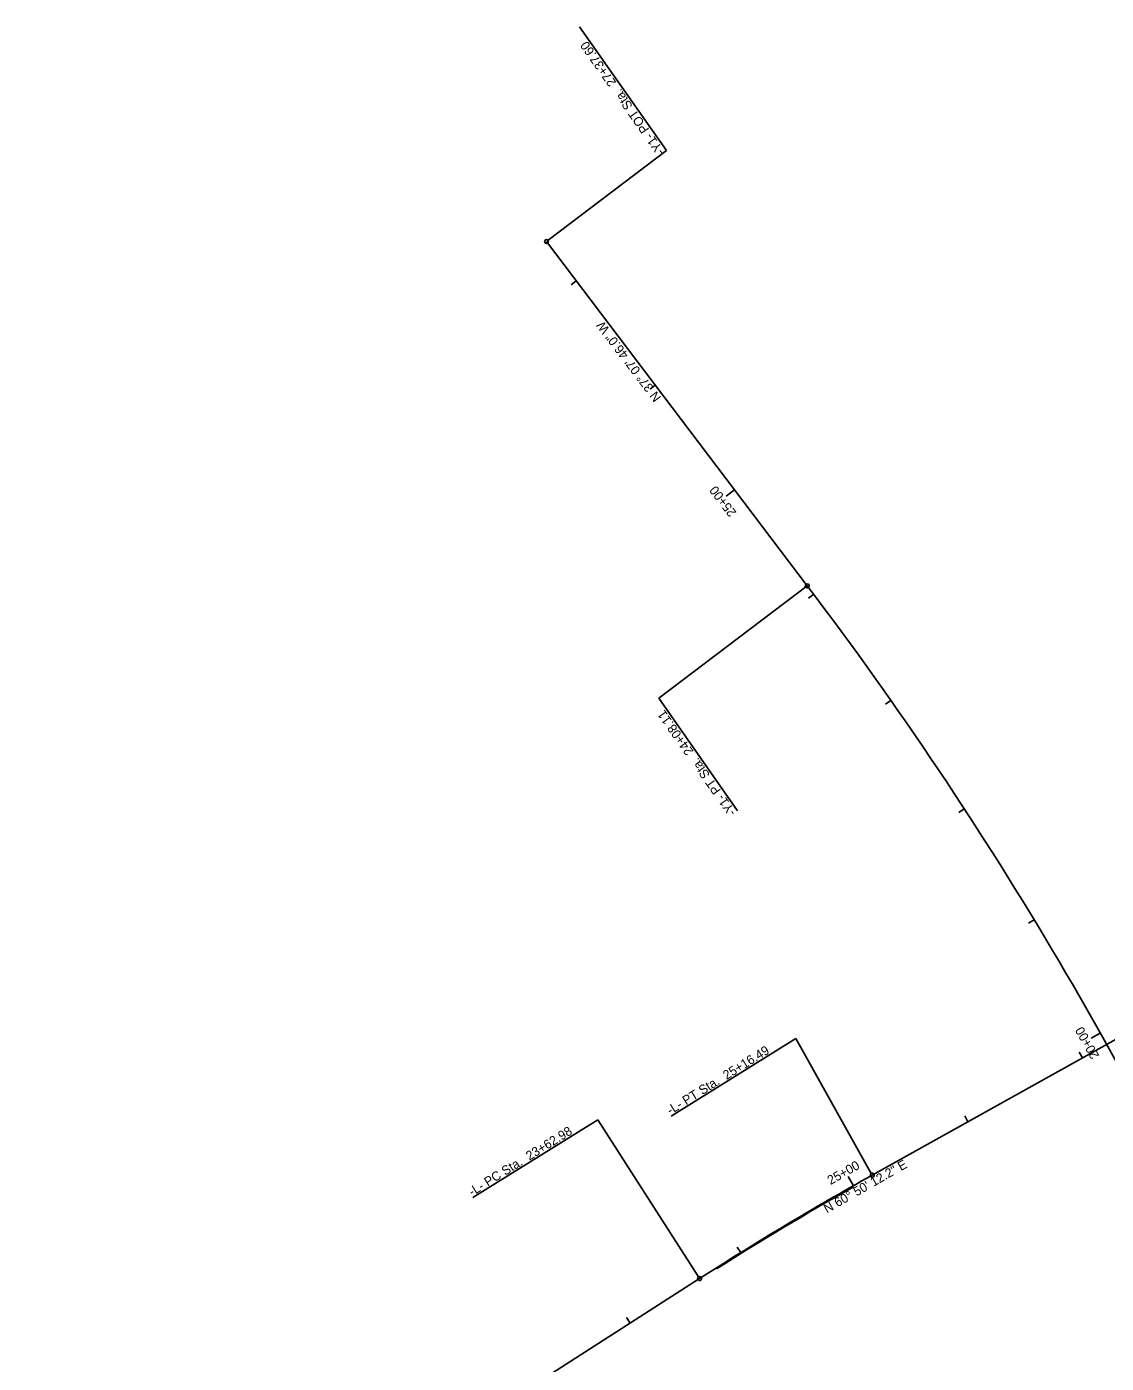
# Model space of a CAD drawing. Extents: x 2045940 to 2048976, y 757914 to 760106.
# Drawn here: x 2046677 to 2047500, y 758615 to 759634 of the extents above; entities that cross this region are included whole.
import ezdxf

# ---------------------------------------------------------------- set-up
doc = ezdxf.new("R2010")
doc.units = 0
for name, color, linetype in [('Prop Conc 1ft 6in Curb and Gutter', 7, 'Continuous'), ('Prop Conc 5in Monolithic Surface Mount Island', 7, 'Continuous'), ('Prop Dimension', 7, 'Continuous'), ('Prop Horizontal Alignment', 7, 'Continuous'), ('Prop Lane Lines', 7, 'Continuous'), ('Prop Terminator CELL', 7, 'Continuous'), ('Typical Terminator CELL', 7, 'Continuous')]:
    doc.layers.add(name, color=color, linetype=linetype)

msp = doc.modelspace()

# ---------------------------------------------------------------- linework, layer by layer
at = {"layer": 'Prop Conc 1ft 6in Curb and Gutter'}
for p, q in [((2047165, 759539.9), (2047098.6, 759634.4)), ((2047074.7, 759471.5), (2047165, 759539.9)), ((2047159.1, 759122.2), (2047272.4, 759207.9)), ((2047219.3, 759036.4), (2047159.1, 759122.2)), ((2047168.5, 758803.5), (2047263.7, 758862.8)), ((2047321.2, 758759.8), (2047263.7, 758862.8)), ((2047017.3, 758741.3), (2047112.6, 758800.7)), ((2047189.5, 758680.9), (2047112.6, 758800.7))]:
    msp.add_line(p, q, dxfattribs=at)
for centre in [(2047073.5, 759470.6), (2047272.4, 759207.9), (2047322, 758758.5), (2047190.3, 758679.6)]:
    msp.add_circle(centre, 1.5, dxfattribs=at)
at = {"layer": 'Prop Dimension'}
for p, q in [((2047216.9, 759281.2), (2047210.5, 759276.4)), ((2047495.9, 758866.8), (2047488.9, 758862.9)), ((2047307.6, 758750.4), (2047303.7, 758757.4))]:
    msp.add_line(p, q, dxfattribs=at)
at = {"layer": 'Prop Horizontal Alignment'}
for p, q in [((2047272.4, 759207.9), (2047073.5, 759470.6)), ((2047272.4, 759207.9), (2047073.5, 759470.6)), ((2047322, 758758.5), (2047734.2, 758988.6)), ((2046677.1, 758350.4), (2047190.3, 758679.6))]:
    msp.add_line(p, q, dxfattribs=at)
for centre, radius, start, end in [((2044880.6, 757397.1), 3000, 23.9646, 37.1294), ((2044880.6, 757397.1), 3000, 23.9646, 37.1294), ((2048540.2, 756575.4), 2500, 119.1633, 122.6814)]:
    msp.add_arc(centre, radius, start, end, dxfattribs=at)
at = {"layer": 'Prop Terminator CELL'}
for p, q in [((2047096.2, 759440.7), (2047092.2, 759437.6)), ((2047156.5, 759360.9), (2047152.6, 759357.9)), ((2047277.3, 759201.5), (2047273.3, 759198.5)), ((2047336.1, 759120.6), (2047332, 759117.7)), ((2047392.1, 759037.8), (2047388, 759035.1)), ((2047445.4, 758953.2), (2047441.2, 758950.6)), ((2047482.2, 758847.9), (2047479.8, 758852.3)), ((2047394.9, 758799.2), (2047392.5, 758803.6)), ((2047221.6, 758699.4), (2047219, 758703.6)), ((2047137.3, 758645.6), (2047134.6, 758649.8))]:
    msp.add_line(p, q, dxfattribs=at)
at = {"layer": 'Typical Terminator CELL'}
msp.add_arc((2048283.9, 757001.6), 2002, 119.1813, 122.6679, dxfattribs=at)

# ---------------------------------------------------------------- texts
at = {"layer": 'Prop Conc 1ft 6in Curb and Gutter'}
for s, rotation, p in [('-Y1- POT Sta.  27+37.60', 125.0514, (2047163.8, 759539.5)), ('-Y1- PT Sta.  24+08.11', 125.0514, (2047218.5, 759035.3)), ('-L- PT Sta.  25+16.49', 31.9194, (2047168, 758804.3)), ('-L- PC Sta.  23+62.98', 31.9194, (2047016.8, 758742.2))]:
    msp.add_text(s, height=7, rotation=rotation, dxfattribs=at).set_placement(p)
at = {"layer": 'Prop Conc 5in Monolithic Surface Mount Island'}
for s, rotation, p in [('25+00', 127.1294, (2047218.7, 759263.9)), ('20+00', 119.3351, (2047495.3, 758849.5)), ('25+00', 29.5412, (2047290.2, 758750.9))]:
    msp.add_text(s, height=7, rotation=rotation, dxfattribs=at).set_placement(p)
at = {"layer": 'Prop Lane Lines'}
for s, rotation, p in [('N 37%%d 07\' 46.0" W', 127.1294, (2047161.3, 759351.6)), ('N 60%%d 50\' 12.2" E', 29.7678, (2047287.4, 758729.2))]:
    msp.add_text(s, height=7, rotation=rotation, dxfattribs=at).set_placement(p)

doc.saveas('drawing.dxf')
